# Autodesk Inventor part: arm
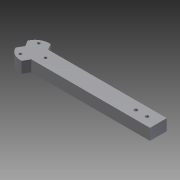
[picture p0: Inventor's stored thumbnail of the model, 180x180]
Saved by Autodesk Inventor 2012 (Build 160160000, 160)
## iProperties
Created: 2011-06
Part Number: arm
Document SubType Name: Modeling
Designer: Bruce
Density: 1 g/cm^3
Material: Default
arm_width: 15.000 mm
arm_height: 10.000 mm
Author: Bruce
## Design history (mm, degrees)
sketch "Sketch1" dims "d1" = 26 (= motor_mount_d)
  geometry: L1 (0, 0)-(0, 57.034); L2 (-110, 0)-(-110, 54.61); L3 (0, 0)-(-110, 0); L4 (0, 7.5)-(-105.67, 7.5); L5 (0, -7.5)-(-105.67, -7.5); L6 (-110, 0)-(-98.742, 6.5); L7 (-110, 0)-(-116.5, 11.258); L8 (-110, 0)-(-98.742, -6.5); L9 (-110, 0)-(-116.5, -11.258); L10 (0, 7.5)-(0, -7.5); L11 (-108.814, 12.946)-(-105.67, 7.5); L12 (-121.804, 5.446)-(-118.66, 0); L13 (-121.804, -5.446)-(-118.66, 0); L14 (-108.814, -12.946)-(-105.67, -7.5); C1 r 1.25 at (-114.75, 8.227); C2 r 1.25 at (-114.75, -8.227); C3 r 1.25 at (-100.5, 0); C4 r 1.5 at (-10, 0); C5 r 1.5 at (-20, 0); 2 further points
  constraints: 28 end point, 8 point on line, 7 parallel, 5 centre point, 1 coincident, 1 collinear, 1 perpendicular, 1 vertical, 12 other
  dimensions: "d0" = 110 distance between parallel lines of L1 L2 (= arm_base_to_motor); "d2" = 7.5 distance between parallel lines of L3 L4 (= 0.5 x arm_width); "d3" = 7.5 distance between parallel lines of L5 L3 (= 0.5 x arm_width); "d4" = 30 deg angle of L3 L6; "d5" = 120 deg angle of L3 L7; "d6" = 9.5 distance from line of L6 C1.centre (= motor_fixing_h); "d7" = 30 deg angle of L3 L8; "d8" = 120 deg angle of L3 L9; "d9" = 9.5 distance from line of C2.centre L8 (= motor_fixing_h); "d10" = 9.5 distance from line of C3.centre L2 (= motor_fixing_h); "d11" = 2.5 diameter of C1 (= motor_fixing_bolt_d); "d12" = 2.5 diameter of C2 (= motor_fixing_bolt_d); "d13" = 2.5 diameter of C3 (= motor_fixing_bolt_d); "d17" = 3 diameter of C5 (= arm_bolt_d); "d18" = 3 diameter of C4 (= arm_bolt_d); "d19" = 10 distance of C4.centre C5.centre (= arm_fixing_Spacing); "d20" = 10 distance from line of L1 C4.centre (= arm_fixing_Spacing); "d26" = 7.5 distance between parallel lines of L9 L13 (= 0.5 x arm_width); "d27" = 7.5 distance between parallel lines of L14 L9 (= 0.5 x arm_width); "d28" = 7.5 distance between parallel lines of L7 L11 (= 0.5 x arm_width); "d29" = 7.5 distance between parallel lines of L12 L7 (= 0.5 x arm_width)
extrude "Extrusion1" new body sketch "Sketch1" distance "d15" = 10 (= arm_height); taper "d16" = 0 deg
sketch "Sketch2"
  geometry: L1 (0, -7.5)-(-105.67, -7.5) reference; L2 (-105.67, 7.5)-(0, 7.5) reference; L3 (-110, -13)-(-17.968, -13); L4 (-123, 0)-(-123, -28.208); L5 (-110, 13)-(-28.065, 13); L6 (-131.44, -0.106)-(-60.729, -70.817); L7 (-131.44, -0.106)-(-60.729, 70.604); L8 (-60.729, -70.817)-(9.982, -0.106); L9 (-60.729, 70.604)-(9.982, -0.106); C1 r 1.5 at (-20, 0) reference; C2 r 1.5 at (-10, 0) reference; C3 r 1.25 at (-100.5, 0) reference; C4 r 1.25 at (-114.75, -8.227) reference; C5 r 1.25 at (-114.75, 8.227) reference; A1 r 13 centre (-110, 0) between (-121.804, -5.446) and (-108.814, -12.946) reference
  constraints: 14 end point, 3 parallel, 3 point on circle, 3 tangent, 2 perpendicular
  dimensions: "d24" = 100 distance between parallel lines of L9 L6; "d25" = 100 distance between parallel lines of L7 L8
body "Solid1"
other parameters: "arm_width" = 15 [user parameter; used in 6 equation terms], "arm_height" = 10 [user parameter; used in 1 equation term], "motor_fixing_h" = 9.5 [user parameter; used in 3 equation terms], "motor_mount_d" = 26 [user parameter; used in 1 equation term], "arm_fixing_Spacing" = 10 [user parameter; used in 3 equation terms], "arm_base_to_motor" = 110 (= 0.5 x motor_to_motor - 0.5 x hub_square + 3 x arm_fixing_Spacing) [user parameter; used in 1 equation term], "motor_fixing_bolt_d" = 2.5 [user parameter; used in 3 equation terms], "arm_bolt_d" = 3 [user parameter; used in 2 equation terms]
